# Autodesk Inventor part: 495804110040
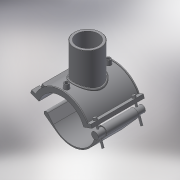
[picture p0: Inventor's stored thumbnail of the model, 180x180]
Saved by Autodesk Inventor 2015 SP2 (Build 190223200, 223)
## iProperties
Created: 2017-07
Part Number: 495804110040
Material: Generic
Description: PLASSON BRANCH SADDLE 110-40
Document SubType Name: Modeling
Designer: KIM
Density: 1 g/cm^3
Appearance: Default
Author: KIM
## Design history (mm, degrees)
derived "495804.ipt"
feature "Solid1::495804.ipt"
feature "Solid2::495804.ipt"
tag "TaggingFeature1"
body "Solid1"
body "Solid2"
other parameters: "d2" = 148, "d3" = 27.5, "d4" = 118, "d5" = 0, "d6" = 0.1, "d8" = 0, "d19" = 6, "d20" = 6, "d21" = 70.8, "d23" = 0, "d24" = 35.4, "d26" = 0, "d27" = 3, "d28" = 3, "d29" = 3, "d30" = 36.66667, "d31" = 6, "d32" = 0, "d33" = 0, "d34" = 0.6, "d40" = 67.6, "d41" = 44, "d43" = 0, "d45" = 0, "d47" = 143, "d50" = 0, "d70" = 15, "d72" = 0, "d73" = 6, "d75" = 5, "d76" = 0, "d77" = 5.5, "d78" = 85, "d79" = 15, "d80" = 47.2, "d82" = 5 deg, "d84" = 4, "d85" = 14, "d86" = 0, "d87" = 3, "d88" = 0, "d89" = 1, "d90" = 1, "d91" = 94.4, "d92" = 0, "d93" = 0.5, "d94" = 57.89474, "d96" = 132.6, "d97" = 2.36, "d98" = 0, "d102" = 1.2, "d103" = 32, "d105" = 0, "d109" = -26, "d117" = 0.4, "d120" = 140 deg, "d121" = 24.228, "d122" = 20 deg, "d124" = 78, "d126" = 0, "d143" = 115.5, "d150" = 19.8, "d159" = 4, "d161" = 2.75, "d162" = 70.8, "d163" = 0, "d167" = 22, "d168" = 59.09091, "d173" = 1, "d175" = 55, "d176" = 20 deg, "d177" = 7.7, "d180" = 0, "d185" = 38.35, "d186" = 38.35, "d187" = 65, "d188" = 6, "d189" = 7.7, "d190" = 0, "d191" = 97.5, "d202" = 0, "d216" = 106.2, "d217" = 0, "d221" = 43.66, "d222" = 7.7, "d223" = 4.62, "d224" = 55, "d225" = 4.62, "d227" = 15.84, "d230" = 68.2, "d236" = 20 deg, "d237" = 72, "d238" = 20 deg, "d239" = 7.7, "B_" = 148, "H_" = 78, "L_" = 118, "d_t" = 6, "H_1" = 68, "d148" = 2.75, "d160" = 2.75
